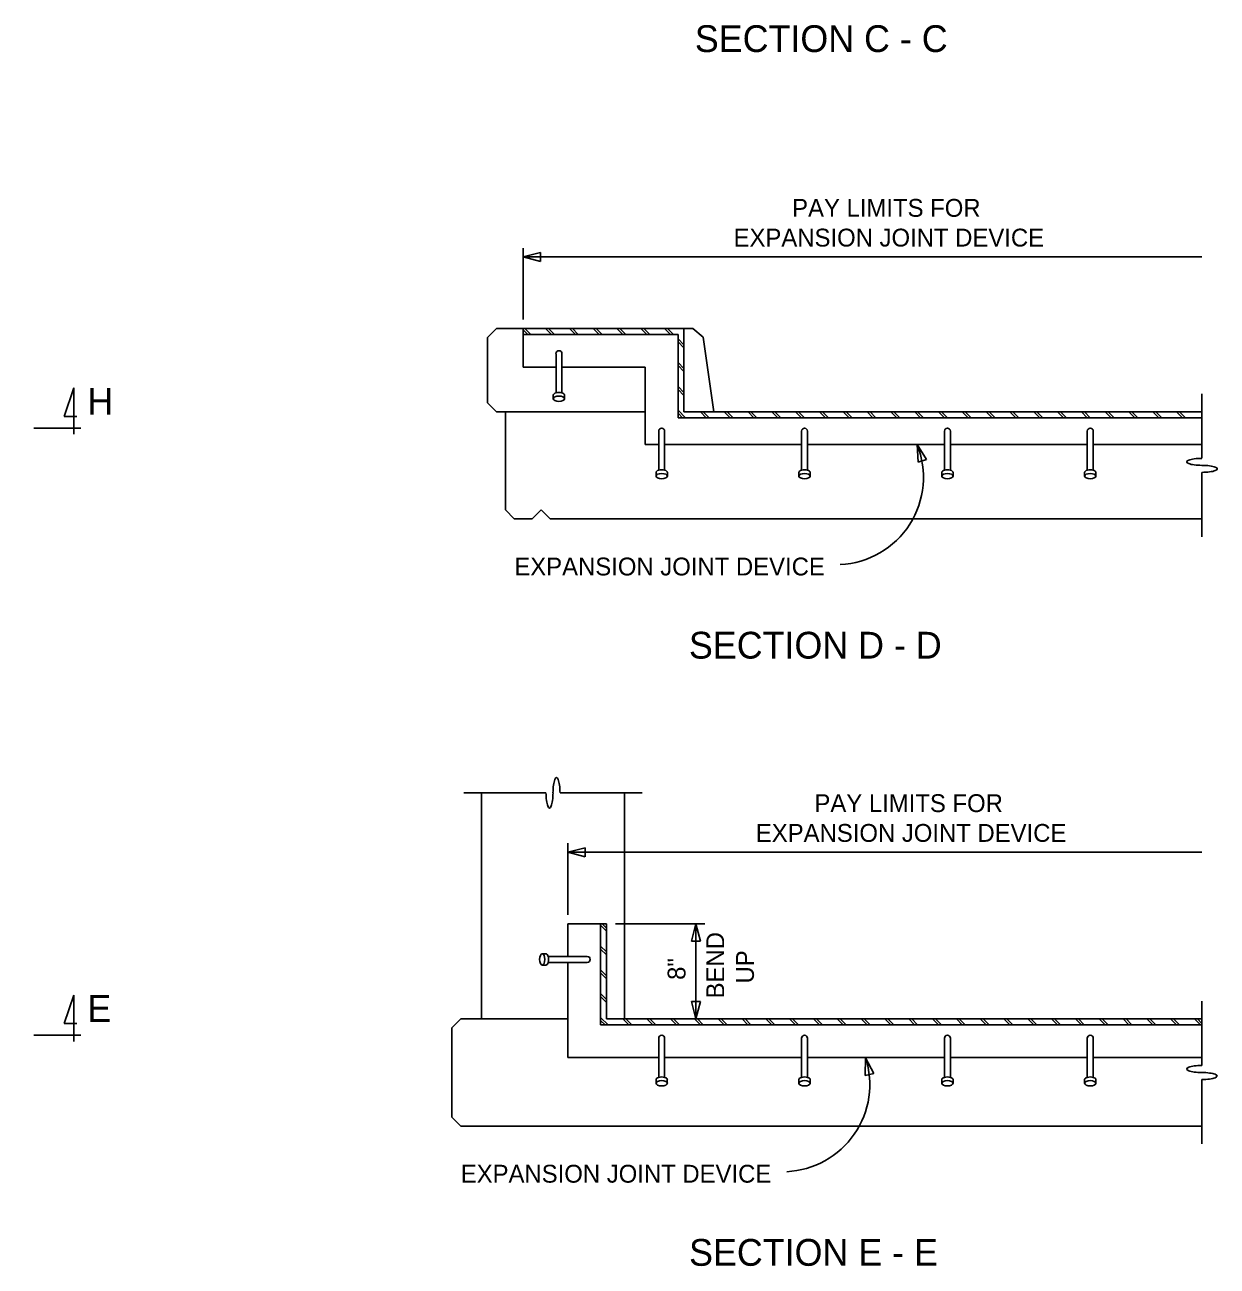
# Model space of a CAD drawing. Extents: x 19590 to 20151, y 19944 to 20103.
# Drawn here: x 19642.26 to 19673.4, y 20017.21 to 20049.64 of the extents above; entities that cross this region are included whole.
import ezdxf

# ---------------------------------------------------------------- set-up
doc = ezdxf.new("R2010")
doc.units = 0
for name, color, linetype in [('DETAIL_PR', 7, 'Continuous'), ('DETAIL_TEXT_DIMEN_PR', 7, 'Continuous'), ('Level 1', 7, 'Continuous'), ('MT_PAVT_MRKGS_EX_REF', 7, 'Continuous')]:
    doc.layers.add(name, color=color, linetype=linetype)

# ---------------------------------------------------------------- blocks, each defined once
blk = doc.blocks.new('BRE')
at = {"layer": 'DETAIL_PR'}
for centre, ratio, start_param, end_param in [((0, 0.098), 0.230206, 4.712389, 7.853982), ((0, -0.098), 0.230204, 1.570796, 4.712389)]:
    blk.add_ellipse(centre, major_axis=(-0.427, 0), ratio=ratio, start_param=start_param, end_param=end_param, dxfattribs=at)
blk = doc.blocks.new('7')
at = {"layer": 'MT_PAVT_MRKGS_EX_REF'}
for p, q in [((-1.499, -0.188), (-1.5, 1.5)), ((-1.5, 1.5), (-1.136, 0.439)), ((0, 0), (-1.738, 0)), ((-1.136, 0.439), (-1.612, 0.439))]:
    blk.add_line(p, q, dxfattribs=at)
blk.add_text('H', height=1, dxfattribs=at).set_placement((-2.5, 0.5))
blk = doc.blocks.new('8')
at = {"layer": 'MT_PAVT_MRKGS_EX_REF'}
for p, q in [((1.5, 1.5), (1.135, 0.439)), ((1.499, -0.227), (1.5, 1.5)), ((0, 0), (1.752, 0)), ((1.135, 0.439), (1.612, 0.439))]:
    blk.add_line(p, q, dxfattribs=at)
blk.add_text('H', height=1, dxfattribs=at).set_placement((2, 0.5))
blk = doc.blocks.new('EJ3D')
at = {"layer": 'DETAIL_PR'}
for p, q in [((28.983, -50.196), (28.983, -52.384)), ((8.689, -50.663), (11.849, -50.663)), ((9.389, -50.663), (9.389, -55.095)), ((9.622, -50.663), (9.622, -55.328)), ((12.216, -50.663), (25.456, -50.663)), ((14.754, -50.663), (14.754, -54.628)), ((14.987, -50.663), (14.987, -54.628)), ((15.298, -50.663), (15.298, -54.628)), ((25.823, -50.663), (29.449, -50.663)), ((28.983, -52.751), (28.983, -57.427)), ((42.001, -54.395), (41.768, -54.628)), ((42.001, -54.395), (42.701, -54.395)), ((42.701, -54.395), (46.9, -54.395)), ((42.701, -55.406), (42.701, -54.395)), ((42.818, -54.551), (42.701, -54.434)), ((42.896, -54.551), (42.74, -54.395)), ((43.44, -54.551), (43.284, -54.395)), ((43.518, -54.551), (43.362, -54.395)), ((44.062, -54.551), (43.906, -54.395)), ((44.14, -54.551), (43.984, -54.395)), ((44.684, -54.551), (44.528, -54.395)), ((44.762, -54.551), (44.606, -54.395)), ((45.306, -54.551), (45.15, -54.395)), ((45.384, -54.551), (45.228, -54.395)), ((45.928, -54.551), (45.772, -54.395)), ((46.006, -54.551), (45.85, -54.395)), ((46.55, -54.551), (46.394, -54.395)), ((46.628, -54.551), (46.472, -54.395)), ((46.9, -54.395), (46.9, -56.572)), ((46.9, -54.395), (47.133, -54.395)), ((47.399, -54.626), (47.133, -54.395)), ((10.322, -54.628), (28.983, -54.628)), ((10.322, -57.272), (10.322, -54.628)), ((14.365, -55.172), (14.365, -54.628)), ((14.521, -55.328), (14.521, -54.628)), ((41.768, -56.339), (41.768, -54.628)), ((42.701, -54.551), (46.744, -54.551)), ((46.744, -54.551), (46.744, -56.728)), ((46.9, -54.823), (46.744, -54.667)), ((46.9, -54.9), (46.744, -54.745)), ((47.399, -54.626), (47.677, -56.572)), ((9.389, -55.095), (10.322, -55.095)), ((9.622, -55.328), (9.389, -55.095)), ((43.557, -55.056), (43.557, -56.076)), ((43.712, -55.056), (43.712, -56.076)), ((9.622, -55.328), (10.322, -55.328)), ((10.322, -55.328), (28.983, -55.328)), ((13.51, -55.328), (13.51, -55.172)), ((13.51, -55.172), (14.365, -55.172)), ((42.701, -55.406), (43.556, -55.406)), ((43.712, -55.406), (45.889, -55.406)), ((45.889, -55.406), (45.889, -57.427)), ((46.9, -55.445), (46.744, -55.289)), ((46.9, -55.522), (46.744, -55.367)), ((46.9, -56.067), (46.744, -55.911)), ((46.9, -56.145), (46.744, -55.989)), ((42.001, -56.572), (41.768, -56.339)), ((43.487, -56.136), (43.487, -56.232)), ((43.782, -56.136), (43.782, -56.232)), ((60.429, -57.788), (60.429, -56.106)), ((9.622, -56.572), (9.389, -56.805)), ((9.622, -56.572), (10.322, -56.572)), ((9.622, -61.237), (9.622, -56.572)), ((10.322, -56.572), (28.983, -56.572)), ((13.51, -56.572), (13.51, -56.727)), ((13.51, -56.727), (14.365, -56.727)), ((14.365, -56.727), (14.365, -57.272)), ((14.521, -56.572), (14.521, -57.272)), ((42.001, -56.572), (45.889, -56.572)), ((42.235, -59.138), (42.235, -56.572)), ((46.939, -56.728), (46.744, -56.533)), ((46.861, -56.728), (46.744, -56.611)), ((46.744, -56.728), (60.429, -56.728)), ((46.9, -56.572), (60.429, -56.572)), ((47.483, -56.728), (47.327, -56.572)), ((47.561, -56.728), (47.405, -56.572)), ((48.105, -56.728), (47.95, -56.572)), ((48.183, -56.728), (48.027, -56.572)), ((48.727, -56.728), (48.572, -56.572)), ((48.805, -56.728), (48.649, -56.572)), ((49.349, -56.728), (49.194, -56.572)), ((49.427, -56.728), (49.271, -56.572)), ((49.971, -56.728), (49.816, -56.572)), ((50.049, -56.728), (49.893, -56.572)), ((50.593, -56.728), (50.438, -56.572)), ((50.671, -56.728), (50.515, -56.572)), ((51.215, -56.728), (51.06, -56.572)), ((51.293, -56.728), (51.137, -56.572)), ((51.837, -56.728), (51.682, -56.572)), ((51.915, -56.728), (51.759, -56.572)), ((52.459, -56.728), (52.304, -56.572)), ((52.537, -56.728), (52.381, -56.572)), ((53.081, -56.728), (52.926, -56.572)), ((53.159, -56.728), (53.003, -56.572)), ((53.703, -56.728), (53.548, -56.572)), ((53.781, -56.728), (53.625, -56.572)), ((54.325, -56.728), (54.17, -56.572)), ((54.403, -56.728), (54.248, -56.572)), ((54.947, -56.728), (54.792, -56.572)), ((55.025, -56.728), (54.87, -56.572)), ((55.569, -56.728), (55.414, -56.572)), ((55.647, -56.728), (55.492, -56.572)), ((56.191, -56.728), (56.036, -56.572)), ((56.269, -56.728), (56.114, -56.572)), ((56.813, -56.728), (56.658, -56.572)), ((56.891, -56.728), (56.736, -56.572)), ((57.435, -56.728), (57.28, -56.572)), ((57.513, -56.728), (57.358, -56.572)), ((58.057, -56.728), (57.902, -56.572)), ((58.135, -56.728), (57.98, -56.572)), ((58.679, -56.728), (58.524, -56.572)), ((58.757, -56.728), (58.602, -56.572)), ((59.301, -56.728), (59.146, -56.572)), ((59.379, -56.728), (59.224, -56.572)), ((59.923, -56.728), (59.768, -56.572)), ((60.001, -56.728), (59.846, -56.572)), ((9.389, -56.805), (10.322, -56.805)), ((9.389, -61.237), (9.389, -56.805)), ((10.322, -57.272), (28.983, -57.272)), ((14.754, -61.237), (14.754, -57.272)), ((14.987, -61.237), (14.987, -57.272)), ((15.298, -61.237), (15.298, -57.272)), ((46.239, -57.078), (46.239, -58.099)), ((46.395, -57.078), (46.395, -58.099)), ((49.971, -57.078), (49.971, -58.099)), ((50.127, -57.078), (50.127, -58.099)), ((53.703, -57.078), (53.703, -58.099)), ((53.859, -57.078), (53.859, -58.099)), ((57.435, -57.078), (57.435, -58.099)), ((57.591, -57.078), (57.591, -58.099)), ((28.983, -59.149), (28.983, -57.427)), ((45.889, -57.427), (46.239, -57.427)), ((46.394, -57.427), (49.971, -57.427)), ((50.127, -57.427), (53.703, -57.427)), ((53.859, -57.427), (57.435, -57.427)), ((57.591, -57.427), (60.429, -57.427)), ((46.169, -58.158), (46.169, -58.253)), ((46.465, -58.158), (46.465, -58.253)), ((49.901, -58.158), (49.901, -58.253)), ((50.197, -58.158), (50.197, -58.253)), ((53.633, -58.158), (53.633, -58.253)), ((53.929, -58.158), (53.929, -58.253)), ((57.365, -58.158), (57.365, -58.253)), ((57.661, -58.158), (57.661, -58.253)), ((60.429, -59.838), (60.429, -58.155)), ((42.235, -59.138), (42.468, -59.371)), ((43.168, -59.138), (42.934, -59.371)), ((43.168, -59.138), (43.401, -59.371)), ((28.983, -59.516), (28.983, -61.704)), ((42.468, -59.371), (42.934, -59.371)), ((43.401, -59.371), (60.429, -59.371)), ((8.689, -61.237), (11.849, -61.237)), ((12.216, -61.237), (25.456, -61.237)), ((25.823, -61.237), (29.449, -61.237))]:
    blk.add_line(p, q, dxfattribs=at)
for centre, radius, start, end in [((43.634, -55.056), 0.0778, 0, 180), ((13.838, -55.263), 0.618, 288.1365, 353.9316), ((14.038, -55.95), 0.101, 94.4387, 265.5613), ((13.838, -56.637), 0.618, 6.0684, 71.8635), ((46.317, -57.078), 0.0778, 0, 180), ((50.049, -57.078), 0.0778, 0, 180), ((53.781, -57.078), 0.0778, 0, 180), ((57.513, -57.078), 0.0778, 0, 180)]:
    blk.add_arc(centre, radius, start, end, dxfattribs=at)
for centre in [(43.634, -56.136), (46.317, -58.157), (50.049, -58.157), (53.781, -58.157), (57.513, -58.157)]:
    blk.add_ellipse(centre, major_axis=(0.148, 0), ratio=0.466726, start_param=0, end_param=3.141593, dxfattribs=at)
for centre in [(43.634, -56.231), (46.317, -58.253), (50.049, -58.253), (53.781, -58.253), (57.513, -58.253)]:
    blk.add_ellipse(centre, major_axis=(0.148, 0), ratio=0.466726, dxfattribs=at)
at = {"layer": 'DETAIL_TEXT_DIMEN_PR'}
for p, q in [((9.389, -50.429), (9.389, -48.563)), ((15.298, -50.429), (15.298, -48.563)), ((9.389, -48.797), (15.298, -48.797)), ((42.701, -54.162), (42.701, -52.296)), ((42.701, -52.529), (60.429, -52.529)), ((21.86, -53.539), (27.117, -53.539)), ((27.116, -53.539), (27.116, -57.272)), ((14.52, -59.527), (14.52, -57.505)), ((13.354, -59.293), (14.52, -59.293)), ((15.298, -59.293), (17.397, -59.293))]:
    blk.add_line(p, q, dxfattribs=at)
for centre, radius, start, end in [((50.873, -58.284), 2.281, 272.7697, 22.0583), ((6.941, -100.072), 39.492, 86.4465, 91.4029), ((17.746, -100.072), 39.492, 91.0778, 93.5535)]:
    blk.add_arc(centre, radius, start, end, dxfattribs=at)
at = {"layer": 'Level 1'}
for p, q in [((9.389, -48.797), (9.841, -48.68)), ((9.841, -48.913), (9.389, -48.797)), ((9.841, -48.68), (9.841, -48.913)), ((14.846, -48.913), (14.846, -48.68)), ((14.846, -48.68), (15.298, -48.797)), ((15.298, -48.797), (14.846, -48.913)), ((42.701, -52.529), (43.153, -52.413)), ((43.153, -52.646), (42.701, -52.529)), ((43.153, -52.413), (43.153, -52.646)), ((27, -55.08), (27.116, -54.628)), ((27.116, -54.628), (27.233, -55.08)), ((27.233, -55.08), (27, -55.08)), ((27, -56.82), (27.233, -56.82)), ((27.116, -57.272), (27, -56.82)), ((27.233, -56.82), (27.116, -57.272)), ((52.987, -57.427), (53.238, -57.821)), ((53.016, -57.893), (52.987, -57.427)), ((53.238, -57.821), (53.016, -57.893)), ((14.069, -59.41), (14.069, -59.177)), ((14.069, -59.177), (14.52, -59.293)), ((14.52, -59.293), (14.069, -59.41)), ((15.298, -59.293), (15.75, -59.177)), ((15.75, -59.41), (15.298, -59.293)), ((15.75, -59.177), (15.75, -59.41)), ((8.932, -60.753), (8.943, -60.52)), ((8.943, -60.52), (9.389, -60.656)), ((15.298, -60.656), (15.743, -60.516)), ((15.743, -60.516), (15.755, -60.749)), ((9.389, -60.656), (8.932, -60.753)), ((15.755, -60.749), (15.298, -60.656))]:
    blk.add_line(p, q, dxfattribs=at)
at = {"layer": 'Level 1', "xscale": 0.9330357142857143, "yscale": 0.9330357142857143}
for p, rotation in [((12.032, -50.663), 90), ((25.639, -50.663), 90), ((28.983, -52.568), 180), ((60.429, -57.972), 180), ((28.983, -59.332), 180), ((12.032, -61.237), 90), ((25.639, -61.237), 90)]:
    blk.add_blockref('BRE', p, dxfattribs=dict(at, rotation=rotation))
at = {"layer": 'Level 1', "xscale": 0.699772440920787, "yscale": 0.699772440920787}
for name, p in [('7', (8.456, -57)), ('8', (29.916, -57))]:
    blk.add_blockref(name, p, dxfattribs=at)
at = {"layer": 'DETAIL_TEXT_DIMEN_PR'}
for s, height, p in [('BRUSH BLOCK', 0.46652, (10.264, -48.524)), ('PAY LIMITS FOR', 0.46652, (49.725, -51.479)), ('EXPANSION JOINT DEVICE', 0.46652, (48.195, -52.256)), ('EXPANSION ', 0.4665, (22.103, -52.497)), ('JOINT DEVICE', 0.46652, (22.103, -53.275)), ('2 1/2"', 0.4665, (16.125, -59.021)), ('BRUSH BLOCK', 0.46652, (3.356, -60.042)), ('FASCIA', 0.4665, (3.356, -60.82)), ('CURB LINE', 0.4665, (17.314, -60.82)), ('EXPANSION JOINT DEVICE', 0.46652, (42.468, -60.848)), ('PLAN AT 2 TUBE, 3 TUBE WITH PICKETS (BRUSH BLOCK)', 0.69987, (3.338, -62.472)), ('SECTION D - D', 0.69987, (47.029, -63.02)), (' & 4 TUBE (BICYCLE) STEEL RAILING', 0.69987, (8.041, -63.405))]:
    blk.add_text(s, height=height, dxfattribs=at).set_placement(p)

msp = doc.modelspace()

# ---------------------------------------------------------------- linework, layer by layer
at = {"layer": 'DETAIL_PR'}
for p, q in [((19653.723, 20029.581), (19655.872, 20029.581)), ((19654.189, 20029.581), (19654.189, 20023.672)), ((19656.239, 20029.581), (19658.388, 20029.581)), ((19657.922, 20029.581), (19657.922, 20023.672)), ((19656.444, 20026.16), (19657.455, 20026.16)), ((19656.444, 20026.16), (19656.444, 20025.305)), ((19657.3, 20026.16), (19657.3, 20023.517)), ((19657.455, 20025.966), (19657.3, 20026.121)), ((19657.455, 20026.044), (19657.338, 20026.16)), ((19657.455, 20026.16), (19657.455, 20023.672)), ((19655.87, 20025.375), (19655.774, 20025.375)), ((19656.95, 20025.305), (19655.93, 20025.305)), ((19657.455, 20025.422), (19657.3, 20025.577)), ((19657.455, 20025.344), (19657.3, 20025.499)), ((19655.87, 20025.08), (19655.774, 20025.08)), ((19656.95, 20025.15), (19655.93, 20025.15)), ((19656.444, 20025.15), (19656.444, 20022.662)), ((19657.455, 20024.8), (19657.3, 20024.955)), ((19657.455, 20024.722), (19657.3, 20024.877)), ((19657.455, 20024.178), (19657.3, 20024.333)), ((19657.455, 20024.1), (19657.3, 20024.255)), ((19673.006, 20022.456), (19673.006, 20024.139)), ((19653.645, 20023.672), (19653.412, 20023.439)), ((19653.645, 20023.672), (19656.444, 20023.672)), ((19657.494, 20023.517), (19657.3, 20023.711)), ((19657.455, 20023.672), (19673.006, 20023.672)), ((19658.038, 20023.517), (19657.883, 20023.672)), ((19658.116, 20023.517), (19657.96, 20023.672)), ((19658.66, 20023.517), (19658.505, 20023.672)), ((19658.738, 20023.517), (19658.582, 20023.672)), ((19659.282, 20023.517), (19659.127, 20023.672)), ((19659.36, 20023.517), (19659.204, 20023.672)), ((19659.904, 20023.517), (19659.749, 20023.672)), ((19659.982, 20023.517), (19659.826, 20023.672)), ((19660.526, 20023.517), (19660.371, 20023.672)), ((19660.604, 20023.517), (19660.448, 20023.672)), ((19661.148, 20023.517), (19660.993, 20023.672)), ((19661.226, 20023.517), (19661.071, 20023.672)), ((19661.77, 20023.517), (19661.615, 20023.672)), ((19661.848, 20023.517), (19661.693, 20023.672)), ((19662.392, 20023.517), (19662.237, 20023.672)), ((19662.47, 20023.517), (19662.315, 20023.672)), ((19663.014, 20023.517), (19662.859, 20023.672)), ((19663.092, 20023.517), (19662.937, 20023.672)), ((19663.636, 20023.517), (19663.481, 20023.672)), ((19663.714, 20023.517), (19663.559, 20023.672)), ((19664.258, 20023.517), (19664.103, 20023.672)), ((19664.336, 20023.517), (19664.181, 20023.672)), ((19664.88, 20023.517), (19664.725, 20023.672)), ((19664.958, 20023.517), (19664.803, 20023.672)), ((19665.502, 20023.517), (19665.347, 20023.672)), ((19665.58, 20023.517), (19665.425, 20023.672)), ((19666.124, 20023.517), (19665.969, 20023.672)), ((19666.202, 20023.517), (19666.047, 20023.672)), ((19666.746, 20023.517), (19666.591, 20023.672)), ((19666.824, 20023.517), (19666.669, 20023.672)), ((19667.369, 20023.517), (19667.213, 20023.672)), ((19667.446, 20023.517), (19667.291, 20023.672)), ((19667.991, 20023.517), (19667.835, 20023.672)), ((19668.068, 20023.517), (19667.913, 20023.672)), ((19668.613, 20023.517), (19668.457, 20023.672)), ((19668.69, 20023.517), (19668.535, 20023.672)), ((19669.235, 20023.517), (19669.079, 20023.672)), ((19669.312, 20023.517), (19669.157, 20023.672)), ((19669.857, 20023.517), (19669.701, 20023.672)), ((19669.934, 20023.517), (19669.779, 20023.672)), ((19670.479, 20023.517), (19670.323, 20023.672)), ((19670.556, 20023.517), (19670.401, 20023.672)), ((19671.101, 20023.517), (19670.945, 20023.672)), ((19671.178, 20023.517), (19671.023, 20023.672)), ((19671.723, 20023.517), (19671.567, 20023.672)), ((19671.8, 20023.517), (19671.645, 20023.672)), ((19672.345, 20023.517), (19672.189, 20023.672)), ((19672.422, 20023.517), (19672.267, 20023.672)), ((19672.967, 20023.517), (19672.811, 20023.672)), ((19673.006, 20023.556), (19672.889, 20023.672)), ((19653.412, 20023.439), (19653.412, 20021.106)), ((19657.416, 20023.517), (19657.3, 20023.633)), ((19657.3, 20023.517), (19673.006, 20023.517)), ((19658.816, 20023.167), (19658.816, 20022.147)), ((19658.971, 20023.167), (19658.971, 20022.147)), ((19662.548, 20023.167), (19662.548, 20022.147)), ((19662.703, 20023.167), (19662.703, 20022.147)), ((19666.28, 20023.167), (19666.28, 20022.147)), ((19666.436, 20023.167), (19666.436, 20022.147)), ((19670.012, 20023.167), (19670.012, 20022.147)), ((19670.168, 20023.167), (19670.168, 20022.147)), ((19656.444, 20022.662), (19658.816, 20022.662)), ((19658.971, 20022.662), (19662.548, 20022.662)), ((19662.704, 20022.662), (19666.28, 20022.662)), ((19666.436, 20022.662), (19670.012, 20022.662)), ((19670.168, 20022.662), (19673.006, 20022.662)), ((19658.746, 20022.087), (19658.746, 20021.991)), ((19659.041, 20022.087), (19659.041, 20021.991)), ((19662.478, 20022.087), (19662.478, 20021.991)), ((19662.773, 20022.087), (19662.773, 20021.991)), ((19666.21, 20022.087), (19666.21, 20021.991)), ((19666.505, 20022.087), (19666.505, 20021.991)), ((19669.942, 20022.087), (19669.942, 20021.991)), ((19670.238, 20022.087), (19670.238, 20021.991)), ((19673.006, 20020.407), (19673.006, 20022.089)), ((19653.645, 20020.873), (19653.412, 20021.106)), ((19653.645, 20020.873), (19673.006, 20020.873))]:
    msp.add_line(p, q, dxfattribs=at)
for centre, start, end in [((19656.95, 20025.227), 270, 90), ((19658.894, 20023.167), 0, 180), ((19662.626, 20023.167), 0, 180), ((19666.358, 20023.167), 0, 180), ((19670.09, 20023.167), 0, 180)]:
    msp.add_arc(centre, 0.0778, start, end, dxfattribs=at)
for centre, major_axis, ratio, start_param, end_param in [((19656.147, 20029.581), (0, -0.398), 0.230204, 1.570796, 4.712389), ((19655.964, 20029.581), (0, -0.398), 0.230206, 4.712389, 7.853982), ((19655.87, 20025.227), (0, -0.148), 0.466726, 0, 3.141593), ((19673.006, 20022.364), (0.398, 0), 0.230204, 1.570796, 4.712389), ((19658.894, 20022.087), (0.148, 0), 0.466726, 0, 3.141593), ((19662.626, 20022.087), (0.148, 0), 0.466726, 0, 3.141593), ((19666.358, 20022.087), (0.148, 0), 0.466726, 0, 3.141593), ((19670.09, 20022.087), (0.148, 0), 0.466726, 0, 3.141593), ((19673.006, 20022.181), (0.398, 0), 0.230206, 4.712389, 7.853982)]:
    msp.add_ellipse(centre, major_axis=major_axis, ratio=ratio, start_param=start_param, end_param=end_param, dxfattribs=at)
for centre, major_axis in [((19655.774, 20025.227), (0, -0.148)), ((19658.894, 20021.992), (0.148, 0)), ((19662.626, 20021.992), (0.148, 0)), ((19666.358, 20021.992), (0.148, 0)), ((19670.09, 20021.992), (0.148, 0))]:
    msp.add_ellipse(centre, major_axis=major_axis, ratio=0.466726, dxfattribs=at)
at = {"layer": 'DETAIL_TEXT_DIMEN_PR'}
for p, q in [((19656.444, 20026.394), (19656.444, 20028.26)), ((19656.444, 20028.027), (19673.006, 20028.027)), ((19657.688, 20026.16), (19660.021, 20026.16)), ((19659.788, 20023.672), (19659.788, 20026.16)), ((19643.542, 20024.294), (19643.287, 20023.552)), ((19643.541, 20023.086), (19643.542, 20024.294)), ((19643.287, 20023.552), (19643.62, 20023.552)), ((19642.492, 20023.245), (19643.718, 20023.245))]:
    msp.add_line(p, q, dxfattribs=at)
msp.add_arc((19662.05, 20021.961), 2.281, 272.7697, 17.8929, dxfattribs=at)
at = {"layer": 'Level 1'}
for p, q in [((19656.444, 20028.026), (19656.896, 20028.143)), ((19656.896, 20027.91), (19656.444, 20028.026)), ((19656.896, 20028.143), (19656.896, 20027.91)), ((19659.671, 20025.708), (19659.788, 20026.16)), ((19659.788, 20026.16), (19659.904, 20025.708)), ((19659.904, 20025.708), (19659.671, 20025.708)), ((19659.904, 20024.124), (19659.671, 20024.124)), ((19659.671, 20024.124), (19659.788, 20023.672)), ((19659.788, 20023.672), (19659.904, 20024.124)), ((19664.221, 20022.661), (19664.211, 20022.195)), ((19664.438, 20022.249), (19664.221, 20022.661)), ((19664.211, 20022.195), (19664.438, 20022.249))]:
    msp.add_line(p, q, dxfattribs=at)

# ---------------------------------------------------------------- block references
msp.add_blockref('EJ3D', (19612.577, 20096.106), dxfattribs=at)

# ---------------------------------------------------------------- texts
at = {"layer": 'DETAIL_TEXT_DIMEN_PR'}
for s, height, p in [('SECTION C - C', 0.69987, (19659.761, 20048.931)), ('PAY LIMITS FOR', 0.46652, (19662.885, 20029.076)), ('EXPANSION JOINT DEVICE', 0.46652, (19661.354, 20028.299)), ('E', 0.7, (19643.892, 20023.594)), ('EXPANSION JOINT DEVICE', 0.46652, (19653.646, 20019.396)), ('SECTION E - E', 0.69987, (19659.61, 20017.224))]:
    msp.add_text(s, height=height, dxfattribs=at).set_placement(p)
for s, p in [('BEND', (19660.526, 20024.209)), ('UP', (19661.304, 20024.599)), ('8"', (19659.516, 20024.693))]:
    msp.add_text(s, height=0.4665, rotation=90, dxfattribs=at).set_placement(p)

doc.saveas('drawing.dxf')
